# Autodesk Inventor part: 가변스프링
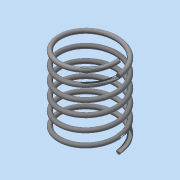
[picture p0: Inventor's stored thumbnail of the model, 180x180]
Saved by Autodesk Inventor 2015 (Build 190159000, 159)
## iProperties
Created: 2018-02
Part Number: 가변스프링
Material: 일반
Document SubType Name: Modeling
Designer: SCD-A011
Density: 1 g/cm^3
Appearance: 기본값
Mass: 5.27371 g
Surface Area: 70.9945 cm^2
Volume: 5.27371 cm^3
Author: SCD-A011
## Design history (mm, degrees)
sketch "스케치1"
  geometry: L1 (0, 0)-(-20, 0); L2 (-20, 0)-(-20, -55.25); L3 (-20, -55.25)-(0, -55.25); L4 (0, -55.25)-(0, 0); C1 r 1.5 at (-20, 0)
  constraints: 8 end point, 2 parallel, 1 centre point, 1 coincident, 1 horizontal, 1 perpendicular
  dimensions: "d0" = 40 diameter of L2 L4; "d1" = 55.25 distance of L1.end L2.end (derived); "d2" = 3 diameter of C1
feature "코일1" pitch "d3" = 10; turns "d5" = 6; dims "d4" = 55.25 (= d1), "d6" = 0, angle "d7" = 90 deg, angle "d8" = 90 deg, "d9" = 0, "d10" = 0
sketch "스케치2"
  geometry: L1 (18.5, 0)-(21.5, 0) reference; 1 further point
  constraints: 1 horizontal alignment
extrude "돌출1" cut sketch "스케치2" distance "d11" = 10; taper "d12" = 0 deg
node "작업 평면1"
sketch "스케치3"
  geometry: L1 (1.5, 0)-(-1.5, 0) reference; 1 further point
  constraints: 1 horizontal alignment
extrude "돌출2" cut sketch "스케치3" distance "d14" = 10; taper "d15" = 0 deg
node "솔리드1"
node "절단 모서리 투영1"
node "절단 모서리 투영2"
other parameters: "d13" = 90 deg
